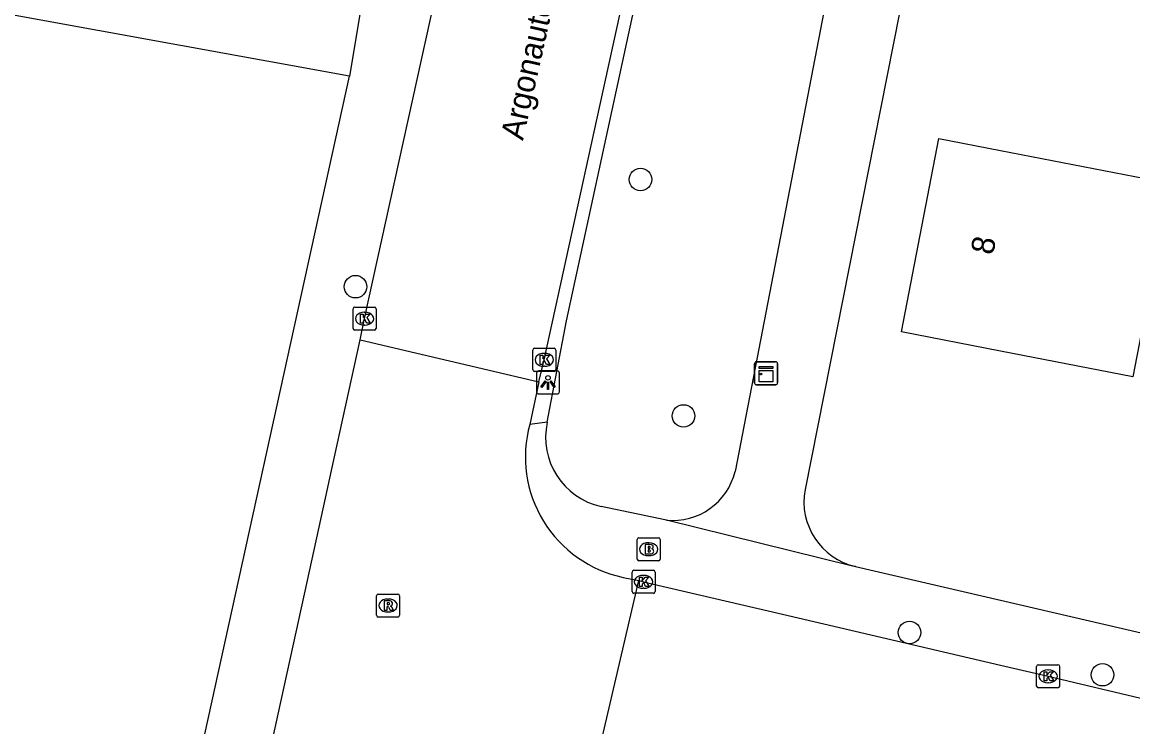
# Model space of a CAD drawing. Extents: x 162186 to 163152, y 385513 to 386513.
# Drawn here: x 162457.49 to 162505.75, y 385785.75 to 385816.36 of the extents above; entities that cross this region are included whole.
import ezdxf

# ---------------------------------------------------------------- set-up
doc = ezdxf.new("R2010")
doc.units = 0
for name, color, linetype in [('IMGEO_Boom', 7, 'Continuous'), ('IMGEO_Brandkraan', 7, 'Continuous'), ('IMGEO_Kast', 7, 'Continuous'), ('IMGEO_Kolk', 7, 'Continuous'), ('IMGEO_Lichtpunt', 7, 'Continuous'), ('IMGEO_Openbare_ruimte_label', 7, 'Continuous'), ('IMGEO_Pand', 7, 'Continuous'), ('IMGEO_Pand_nummerreeks', 7, 'Continuous'), ('IMGEO_Rijbaan_lokaal_gesloten', 7, 'Continuous'), ('IMGEO_Rijbaan_lokaal_open', 7, 'Continuous'), ('IMGEO_Rioolput', 7, 'Continuous'), ('IMGEO_Voetpad_open', 7, 'Continuous')]:
    doc.layers.add(name, color=color, linetype=linetype)

msp = doc.modelspace()

# ---------------------------------------------------------------- linework, layer by layer
at = {"layer": 'IMGEO_Boom'}
for centre in [(162484.361, 385809.529), (162471.97, 385804.875), (162486.226, 385799.258), (162496.048, 385789.85), (162504.438, 385788.015)]:
    msp.add_circle(centre, 0.489, dxfattribs=at)
at = {"layer": 'IMGEO_Brandkraan'}
for p, q in [((162484.214, 385793.042), (162484.214, 385793.894)), ((162484.289, 385793.968), (162485.141, 385793.968)), ((162485.215, 385793.894), (162485.215, 385793.042)), ((162484.702, 385793.748), (162484.727, 385793.748)), ((162485.141, 385792.968), (162484.289, 385792.968)), ((162484.725, 385793.188), (162484.7, 385793.188))]:
    msp.add_line(p, q, dxfattribs=at)
for points in [[(162484.214, 385793.042), (162484.214, 385793.894)], [(162484.289, 385793.968), (162485.141, 385793.968)], [(162485.215, 385793.894), (162485.215, 385793.042)], [(162484.562, 385793.668), (162484.562, 385793.268), (162484.775, 385793.268)], [(162484.793, 385793.668), (162484.562, 385793.668)], [(162484.741, 385793.587), (162484.687, 385793.587), (162484.687, 385793.511)], [(162484.687, 385793.511), (162484.74, 385793.511)], [(162484.749, 385793.435), (162484.687, 385793.435), (162484.687, 385793.354)], [(162485.141, 385792.968), (162484.289, 385792.968)], [(162484.687, 385793.354), (162484.749, 385793.354)]]:
    msp.add_lwpolyline(points, dxfattribs=at)
for centre, radius, start, end in [((162484.291, 385793.892), 0.0765, 91.552, 178.448), ((162484.291, 385793.892), 0.0765, 91.552, 178.448), ((162485.139, 385793.892), 0.0765, 1.552, 88.448), ((162485.139, 385793.892), 0.0765, 1.552, 88.448), ((162484.742, 385793.549), 0.0379, 267.8285, 90.9355), ((162484.75, 385793.394), 0.0404, 269.8759, 90.5077), ((162484.797, 385793.523), 0.145, 59.4692, 91.5367), ((162484.822, 385793.57), 0.0922, 285.5137, 58.1501), ((162484.827, 385793.378), 0.105, 301.3115, 78.989), ((162484.291, 385793.044), 0.0765, 181.552, 268.448), ((162484.291, 385793.044), 0.0765, 181.552, 268.448), ((162484.781, 385793.519), 0.251, 268.6676, 293.5347), ((162485.139, 385793.044), 0.0765, 271.552, 358.448), ((162485.139, 385793.044), 0.0765, 271.552, 358.448)]:
    msp.add_arc(centre, radius, start, end, dxfattribs=at)
for centre, major_axis, ratio, start_param, end_param in [((162484.701, 385793.468), (-0.387, 0.002), 0.722429, 4.712389, 7.853982), ((162484.726, 385793.468), (-0.39, 0.002), 0.717154, 1.570796, 4.712389)]:
    msp.add_ellipse(centre, major_axis=major_axis, ratio=ratio, start_param=start_param, end_param=end_param, dxfattribs=at)
at = {"layer": 'IMGEO_Kast'}
for p, q in [((162489.391, 385801.613), (162490.232, 385801.613)), ((162490.232, 385801.613), (162489.391, 385801.613)), ((162489.316, 385800.688), (162489.316, 385801.529)), ((162489.316, 385801.529), (162489.316, 385800.688)), ((162490.316, 385801.538), (162490.316, 385800.697)), ((162490.316, 385800.697), (162490.316, 385801.538)), ((162490.241, 385800.613), (162489.4, 385800.613)), ((162489.4, 385800.613), (162490.241, 385800.613))]:
    msp.add_line(p, q, dxfattribs=at)
for points in [[(162489.511, 385801.403), (162490.111, 385801.403), (162490.111, 385801.318), (162489.511, 385801.318), (162489.511, 385801.403)], [(162489.511, 385801.228), (162490.111, 385801.228), (162490.111, 385800.739), (162489.511, 385800.739), (162489.511, 385801.228)]]:
    msp.add_lwpolyline(points, dxfattribs=at)
msp.add_circle((162489.595, 385801.077), 0.0377, dxfattribs=at)
for centre, start, end in [((162489.394, 385801.535), 92.4484, 184.2845), ((162489.394, 385801.535), 92.4484, 184.2845), ((162490.238, 385801.535), 2.4484, 94.2845), ((162490.238, 385801.535), 2.4484, 94.2845), ((162489.394, 385800.691), 182.4484, 274.2845), ((162489.394, 385800.691), 182.4484, 274.2845), ((162490.238, 385800.691), 272.4484, 4.2845), ((162490.238, 385800.691), 272.4484, 4.2845)]:
    msp.add_arc(centre, 0.0779, start, end, dxfattribs=at)
at = {"layer": 'IMGEO_Kolk'}
for p, q in [((162471.866, 385803.06), (162471.866, 385803.912)), ((162471.941, 385803.986), (162472.793, 385803.986)), ((162472.354, 385803.766), (162472.379, 385803.766)), ((162472.867, 385803.912), (162472.867, 385803.06)), ((162472.377, 385803.206), (162472.352, 385803.206)), ((162472.793, 385802.986), (162471.941, 385802.986)), ((162479.676, 385801.27), (162479.676, 385802.122)), ((162479.751, 385802.196), (162480.603, 385802.196)), ((162480.677, 385802.122), (162480.677, 385801.27)), ((162480.164, 385801.976), (162480.189, 385801.976)), ((162480.603, 385801.196), (162479.751, 385801.196)), ((162480.187, 385801.416), (162480.162, 385801.416)), ((162483.989, 385791.626), (162483.989, 385792.478)), ((162484.064, 385792.552), (162484.916, 385792.552)), ((162484.99, 385792.478), (162484.99, 385791.626)), ((162484.477, 385792.332), (162484.502, 385792.332)), ((162484.916, 385791.552), (162484.064, 385791.552)), ((162484.5, 385791.772), (162484.475, 385791.772)), ((162501.575, 385787.522), (162501.575, 385788.374)), ((162501.65, 385788.448), (162502.502, 385788.448)), ((162502.063, 385788.228), (162502.088, 385788.228)), ((162502.576, 385788.374), (162502.576, 385787.522)), ((162502.086, 385787.668), (162502.061, 385787.668)), ((162502.502, 385787.448), (162501.65, 385787.448))]:
    msp.add_line(p, q, dxfattribs=at)
for points in [[(162471.866, 385803.06), (162471.866, 385803.912)], [(162471.941, 385803.986), (162472.793, 385803.986)], [(162472.187, 385803.686), (162472.31, 385803.686), (162472.31, 385803.535), (162472.44, 385803.686), (162472.604, 385803.686), (162472.458, 385803.535), (162472.611, 385803.286), (162472.459, 385803.286), (162472.374, 385803.45), (162472.31, 385803.383), (162472.31, 385803.286), (162472.187, 385803.286), (162472.187, 385803.686)], [(162472.867, 385803.912), (162472.867, 385803.06)], [(162472.793, 385802.986), (162471.941, 385802.986)], [(162479.676, 385801.27), (162479.676, 385802.122)], [(162479.751, 385802.196), (162480.603, 385802.196)], [(162480.677, 385802.122), (162480.677, 385801.27)], [(162479.997, 385801.896), (162480.12, 385801.896), (162480.12, 385801.745), (162480.25, 385801.896), (162480.414, 385801.896), (162480.268, 385801.745), (162480.421, 385801.496), (162480.269, 385801.496), (162480.184, 385801.66), (162480.12, 385801.593), (162480.12, 385801.496), (162479.997, 385801.496), (162479.997, 385801.896)], [(162480.603, 385801.196), (162479.751, 385801.196)], [(162483.989, 385791.626), (162483.989, 385792.478)], [(162484.064, 385792.552), (162484.916, 385792.552)], [(162484.99, 385792.478), (162484.99, 385791.626)], [(162484.31, 385792.252), (162484.433, 385792.252), (162484.433, 385792.101), (162484.563, 385792.252), (162484.727, 385792.252), (162484.581, 385792.101), (162484.734, 385791.852), (162484.582, 385791.852), (162484.497, 385792.016), (162484.433, 385791.949), (162484.433, 385791.852), (162484.31, 385791.852), (162484.31, 385792.252)], [(162484.916, 385791.552), (162484.064, 385791.552)], [(162501.575, 385787.522), (162501.575, 385788.374)], [(162501.65, 385788.448), (162502.502, 385788.448)], [(162501.896, 385788.148), (162502.019, 385788.148), (162502.019, 385787.997), (162502.149, 385788.148), (162502.313, 385788.148), (162502.167, 385787.997), (162502.32, 385787.748), (162502.168, 385787.748), (162502.083, 385787.912), (162502.019, 385787.845), (162502.019, 385787.748), (162501.896, 385787.748), (162501.896, 385788.148)], [(162502.576, 385788.374), (162502.576, 385787.522)], [(162502.502, 385787.448), (162501.65, 385787.448)]]:
    msp.add_lwpolyline(points, dxfattribs=at)
for centre, start, end in [((162471.943, 385803.91), 91.552, 178.448), ((162471.943, 385803.91), 91.552, 178.448), ((162472.791, 385803.91), 1.552, 88.448), ((162472.791, 385803.91), 1.552, 88.448), ((162471.943, 385803.062), 181.552, 268.448), ((162471.943, 385803.062), 181.552, 268.448), ((162472.791, 385803.062), 271.552, 358.448), ((162472.791, 385803.062), 271.552, 358.448), ((162479.753, 385802.12), 91.552, 178.448), ((162479.753, 385802.12), 91.552, 178.448), ((162480.601, 385802.12), 1.552, 88.448), ((162480.601, 385802.12), 1.552, 88.448), ((162479.753, 385801.272), 181.552, 268.448), ((162479.753, 385801.272), 181.552, 268.448), ((162480.601, 385801.272), 271.552, 358.448), ((162480.601, 385801.272), 271.552, 358.448), ((162484.066, 385792.476), 91.552, 178.448), ((162484.066, 385792.476), 91.552, 178.448), ((162484.914, 385792.476), 1.552, 88.448), ((162484.914, 385792.476), 1.552, 88.448), ((162484.066, 385791.628), 181.552, 268.448), ((162484.066, 385791.628), 181.552, 268.448), ((162484.914, 385791.628), 271.552, 358.448), ((162484.914, 385791.628), 271.552, 358.448), ((162501.652, 385788.372), 91.552, 178.448), ((162501.652, 385788.372), 91.552, 178.448), ((162502.5, 385788.372), 1.552, 88.448), ((162502.5, 385788.372), 1.552, 88.448), ((162501.652, 385787.524), 181.552, 268.448), ((162501.652, 385787.524), 181.552, 268.448), ((162502.5, 385787.524), 271.552, 358.448), ((162502.5, 385787.524), 271.552, 358.448)]:
    msp.add_arc(centre, 0.0765, start, end, dxfattribs=at)
for centre, major_axis, ratio, start_param, end_param in [((162472.353, 385803.486), (-0.387, 0.002), 0.722429, 4.712389, 7.853982), ((162472.378, 385803.486), (-0.39, 0.002), 0.717154, 1.570796, 4.712389), ((162480.163, 385801.696), (-0.387, 0.002), 0.722429, 4.712389, 7.853982), ((162480.188, 385801.696), (-0.39, 0.002), 0.717154, 1.570796, 4.712389), ((162484.476, 385792.052), (-0.387, 0.002), 0.722429, 4.712389, 7.853982), ((162484.501, 385792.052), (-0.39, 0.002), 0.717154, 1.570796, 4.712389), ((162502.062, 385787.948), (-0.387, 0.002), 0.722429, 4.712389, 7.853982), ((162502.087, 385787.948), (-0.39, 0.002), 0.717154, 1.570796, 4.712389)]:
    msp.add_ellipse(centre, major_axis=major_axis, ratio=ratio, start_param=start_param, end_param=end_param, dxfattribs=at)
at = {"layer": 'IMGEO_Lichtpunt'}
for p, q in [((162479.839, 385801.117), (162479.839, 385800.31)), ((162479.839, 385801.117), (162479.839, 385800.31)), ((162480.741, 385801.212), (162479.933, 385801.212)), ((162480.741, 385801.212), (162479.933, 385801.212)), ((162480.835, 385800.31), (162480.835, 385801.117)), ((162480.835, 385800.31), (162480.835, 385801.117)), ((162479.933, 385800.216), (162480.741, 385800.216)), ((162479.933, 385800.216), (162480.741, 385800.216))]:
    msp.add_line(p, q, dxfattribs=at)
for points in [[(162480.213, 385800.781), (162480.252, 385800.753), (162480.064, 385800.491), (162480.026, 385800.518), (162480.213, 385800.781)], [(162480.315, 385800.733), (162480.362, 385800.733), (162480.362, 385800.411), (162480.315, 385800.411), (162480.315, 385800.733)], [(162480.425, 385800.753), (162480.463, 385800.78), (162480.65, 385800.518), (162480.611, 385800.49), (162480.425, 385800.753)]]:
    msp.add_lwpolyline(points, dxfattribs=at)
msp.add_circle((162480.338, 385800.915), 0.0994, dxfattribs=at)
for centre, start, end in [((162479.933, 385801.117), 90, 180), ((162479.933, 385801.117), 90, 180), ((162480.741, 385801.117), 0, 90), ((162480.741, 385801.117), 0, 90), ((162479.933, 385800.31), 180, 270), ((162479.933, 385800.31), 180, 270), ((162480.741, 385800.31), 270, 0), ((162480.741, 385800.31), 270, 360)]:
    msp.add_arc(centre, 0.0946, start, end, dxfattribs=at)
at = {"layer": 'IMGEO_Pand'}
msp.add_lwpolyline([(162509.518, 385804.576), (162506.564, 385805.149), (162505.753, 385800.963), (162500, 385802.077), (162495.697, 385802.911), (162497.324, 385811.308), (162500, 385810.789), (162510.334, 385808.787), (162509.518, 385804.576)], dxfattribs=at)
at = {"layer": 'IMGEO_Rijbaan_lokaal_gesloten'}
for points in [[(162472.173, 385802.564), (162472.364, 385803.485), (162476.155, 385820.726), (162481.676, 385845.76), (162484.436, 385858.393), (162484.5, 385858.619)], [(162479.937, 385800.744), (162480.172, 385801.696), (162483.694, 385817.751), (162486.981, 385833.418)]]:
    msp.add_lwpolyline(points, dxfattribs=at)
at = {"layer": 'IMGEO_Rijbaan_lokaal_open'}
for points in [[(162467.367, 385780.629), (162469.886, 385792.111), (162470.666, 385795.682), (162470.931, 385796.883), (162472.173, 385802.564)], [(162472.173, 385802.564), (162479.937, 385800.744)], [(162479.937, 385800.744), (162479.544, 385798.893)], [(162482.693, 385785.277), (162484.279, 385792.112)], [(162483.608, 385792.245), (162484.279, 385792.112)], [(162484.279, 385792.112), (162484.485, 385792.051), (162490.534, 385790.64), (162500, 385788.431), (162502.072, 385787.947), (162511.289, 385785.773)]]:
    msp.add_lwpolyline(points, dxfattribs=at)
msp.add_arc((162484.701, 385797.479), 5.347, 164.6722, 258.2036, dxfattribs=at)
at = {"layer": 'IMGEO_Rioolput'}
for p, q in [((162472.961, 385791.522), (162473.813, 385791.522)), ((162472.886, 385790.596), (162472.886, 385791.448)), ((162473.374, 385791.302), (162473.399, 385791.302)), ((162473.887, 385791.448), (162473.887, 385790.596)), ((162473.813, 385790.522), (162472.961, 385790.522)), ((162473.397, 385790.742), (162473.372, 385790.742))]:
    msp.add_line(p, q, dxfattribs=at)
for points in [[(162472.961, 385791.522), (162473.813, 385791.522)], [(162472.886, 385790.596), (162472.886, 385791.448)], [(162473.475, 385791.22), (162473.223, 385791.222), (162473.223, 385790.822)], [(162473.223, 385790.822), (162473.347, 385790.822), (162473.347, 385790.984), (162473.358, 385790.984)], [(162473.401, 385791.141), (162473.347, 385791.141), (162473.347, 385791.06)], [(162473.347, 385791.06), (162473.399, 385791.06)], [(162473.887, 385791.448), (162473.887, 385790.596)], [(162473.813, 385790.522), (162472.961, 385790.522)], [(162473.405, 385790.955), (162473.476, 385790.822), (162473.616, 385790.822), (162473.551, 385790.948)]]:
    msp.add_lwpolyline(points, dxfattribs=at)
for centre, radius, start, end in [((162472.963, 385791.446), 0.0765, 91.552, 178.448), ((162472.963, 385791.446), 0.0765, 91.552, 178.448), ((162473.811, 385791.446), 0.0765, 1.552, 88.448), ((162473.811, 385791.446), 0.0765, 1.552, 88.448), ((162473.357, 385790.931), 0.0533, 26.0293, 88.6989), ((162473.383, 385791.249), 0.19, 274.7715, 282.9687), ((162473.407, 385791.045), 0.0964, 77.0061, 93.1865), ((162473.421, 385791.102), 0.0378, 276.6634, 79.6772), ((162473.474, 385791.11), 0.109, 350.3612, 89.416), ((162473.472, 385791.11), 0.112, 277.5842, 350.9817), ((162473.456, 385790.895), 0.108, 29.5134, 73.7905), ((162472.963, 385790.598), 0.0765, 181.552, 268.448), ((162472.963, 385790.598), 0.0765, 181.552, 268.448), ((162473.811, 385790.598), 0.0765, 271.552, 358.448), ((162473.811, 385790.598), 0.0765, 271.552, 358.448)]:
    msp.add_arc(centre, radius, start, end, dxfattribs=at)
for centre, major_axis, ratio, start_param, end_param in [((162473.373, 385791.022), (-0.387, 0.002), 0.722429, 4.712389, 7.853982), ((162473.398, 385791.022), (-0.39, 0.002), 0.717154, 1.570796, 4.712389)]:
    msp.add_ellipse(centre, major_axis=major_axis, ratio=ratio, start_param=start_param, end_param=end_param, dxfattribs=at)
at = {"layer": 'IMGEO_Voetpad_open'}
for points in [[(162503.373, 385856.006), (162500, 385838.961), (162491.51, 385796.057)], [(162488.296, 385834.094), (162495.395, 385832.741), (162488.47, 385796.85)], [(162480.302, 385798.982), (162481.141, 385803.386), (162487.623, 385833.272)], [(162471.711, 385814.014), (162438.716, 385820.018), (162429.363, 385821.72), (162425.367, 385822.443), (162418.614, 385823.681)], [(162472.197, 385816.96), (162471.711, 385814.014)], [(162451.431, 385721.992), (162451.536, 385722.303), (162451.611, 385722.618), (162457.633, 385750), (162471.711, 385814.014)], [(162480.302, 385798.982), (162479.544, 385798.893)], [(162485.484, 385794.728), (162482.65, 385795.32)], [(162493.7, 385792.713), (162493.571, 385792.73), (162485.484, 385794.728)], [(162493.7, 385792.713), (162500, 385791.251), (162664.68, 385753.025), (162666.341, 385752.639)]]:
    msp.add_lwpolyline(points, dxfattribs=at)
for centre, radius, start, end in [((162483.325, 385798.337), 3.091, 167.9526, 257.3817), ((162485.758, 385797.504), 2.789, 264.3543, 346.4446), ((162494.352, 385795.529), 2.89, 169.4731, 256.9688)]:
    msp.add_arc(centre, radius, start, end, dxfattribs=at)

# ---------------------------------------------------------------- texts
at = {"layer": 'IMGEO_Openbare_ruimte_label'}
msp.add_text('Argonautenlaan', height=1, rotation=77.409, dxfattribs=at).set_placement((162479.249, 385811.198))
at = {"layer": 'IMGEO_Pand_nummerreeks'}
msp.add_text('8', height=1, rotation=79.0343, dxfattribs=at).set_placement((162499.679, 385806.22))

doc.saveas('drawing.dxf')
